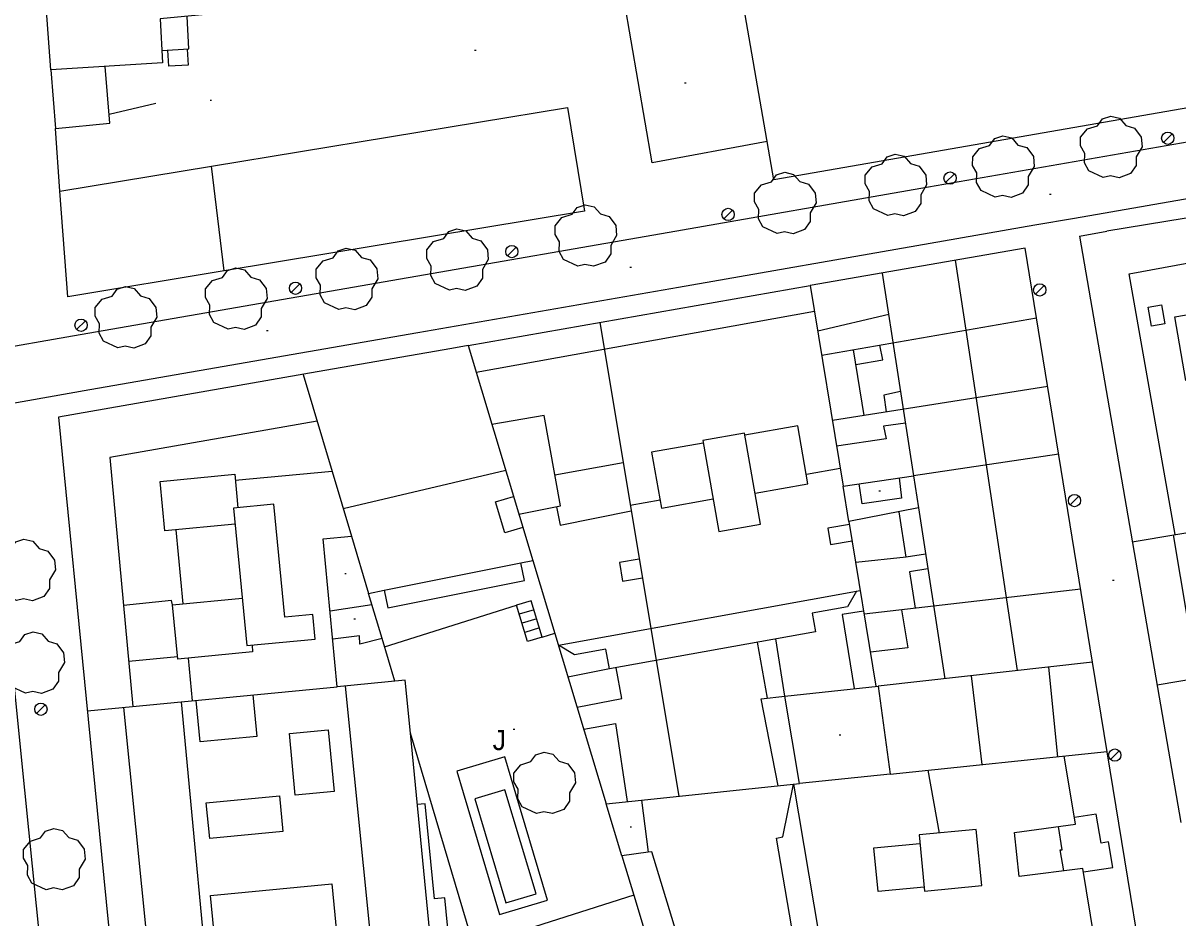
# Model space of a CAD drawing. Extents: x 431390 to 432653, y 4586754 to 4589600.
# Drawn here: x 431870.2 to 431945.3, y 4586880.3 to 4586938.4 of the extents above; entities that cross this region are included whole.
import ezdxf

# ---------------------------------------------------------------- set-up
doc = ezdxf.new("R2010")
doc.units = 0
for name, color, linetype in [('COM_17LS_LN', 7, 'Continuous'), ('CON_01_LN', 7, 'Continuous'), ('CON_01FI_LN', 7, 'Continuous'), ('CON_03_LN', 7, 'Continuous'), ('CON_04_LN', 7, 'Continuous'), ('CON_07_LN', 7, 'Continuous'), ('CON_10_LN', 7, 'Continuous'), ('CON_14LS_LN', 7, 'Continuous'), ('CON_15_LN', 7, 'Continuous'), ('CON_16_LN', 7, 'Continuous'), ('CON_17_LN', 7, 'Continuous'), ('CON_23_LN', 7, 'Continuous'), ('CON_29_LN', 7, 'Continuous'), ('ENE_06_PT', 7, 'Continuous'), ('HID_11EX_LN', 7, 'Continuous'), ('HID_11IN_LN', 7, 'Continuous'), ('ORO_03_PT', 7, 'Continuous'), ('TOP_15JA_TX', 7, 'Continuous'), ('VEG_03_PT', 7, 'Continuous'), ('VEG_06_LN', 7, 'Continuous')]:
    doc.layers.add(name, color=color, linetype=linetype)

msp = doc.modelspace()

# ---------------------------------------------------------------- linework, layer by layer
at = {"layer": 'COM_17LS_LN'}
for points in [[(431978.482, 4586940.712), (431979.21, 4586936.465), (431977.301, 4586936.133), (431968.138, 4586934.539), (431952.481, 4586931.815), (431928.554, 4586927.652), (431912.203, 4586924.807), (431895.247, 4586921.857), (431873.934, 4586918.149), (431867.46, 4586917.026), (431866.397, 4586927.581), (431865.787, 4586933.635), (431867.716, 4586933.829), (431867.112, 4586939.828), (431865.183, 4586939.634), (431863.226, 4586959.067), (431861.278, 4586978.415)], [(431938.543, 4586925.736), (431968.756, 4586930.993), (431979.572, 4586932.875)], [(431935.982, 4586925.291), (431938.543, 4586925.736)], [(431874.91, 4586845.69), (431873.853, 4586853.541), (431873.729, 4586854.767), (431875.087, 4586854.904), (431874.927, 4586856.495), (431873.569, 4586856.358), (431870.326, 4586888.559), (431867.823, 4586913.416), (431874.552, 4586914.603), (431895.864, 4586918.311), (431912.821, 4586921.261), (431929.172, 4586924.106), (431935.982, 4586925.291)]]:
    msp.add_lwpolyline(points, dxfattribs=at)
at = {"layer": 'CON_01_LN'}
for points in [[(431969.206, 4586961.566), (431973.29, 4586937.65), (431960.331, 4586935.401), (431960.23, 4586935.985), (431956.915, 4586935.41), (431957.016, 4586934.825), (431919.01, 4586928.23)], [(431872.028, 4586935.375), (431871.13, 4586947.5)], [(431906.713, 4586926.193), (431883.286, 4586922.314)], [(431948.316, 4586926.149), (431940.65, 4586924.889)], [(431938.866, 4586924.564), (431940.65, 4586924.889)], [(431938.866, 4586924.564), (431945.466, 4586886.462)], [(431935.349, 4586923.793), (431921.372, 4586921.348)], [(431939.73, 4586896.87), (431935.349, 4586923.793)], [(431899.135, 4586917.457), (431921.372, 4586921.348)], [(431899.135, 4586917.457), (431898.087, 4586917.274), (431889.328, 4586915.741), (431872.52, 4586912.8), (431874.449, 4586893.185)], [(431906.402, 4586853.218), (431945.07, 4586864.17), (431939.73, 4586896.87)], [(431874.449, 4586893.185), (431876.634, 4586870.968)]]:
    msp.add_lwpolyline(points, dxfattribs=at)
at = {"layer": 'CON_01FI_LN'}
for points in [[(431871.13, 4586947.5), (431902.33, 4586950.93), (431904.113, 4586941.087), (431879.12, 4586938.68), (431879.27, 4586935.82), (431872.028, 4586935.375)], [(431919.01, 4586928.23), (431916.429, 4586943.089)], [(431883.286, 4586922.314), (431882.464, 4586929.119), (431905.59, 4586932.93), (431906.713, 4586926.193)], [(431928.406, 4586906.9), (431923.888, 4586906.031), (431923.511, 4586908.323), (431928.084, 4586908.997), (431928.406, 4586906.9)], [(431902.571, 4586903.326), (431903.349, 4586903.481), (431908.115, 4586887.673), (431910.413, 4586887.913), (431910.843, 4586884.526), (431909.134, 4586884.293), (431909.905, 4586881.735), (431899.52, 4586878.424), (431895.383, 4586892.267), (431895.05, 4586895.7), (431890.638, 4586895.276), (431889.715, 4586904.885), (431891.559, 4586905.062), (431892.668, 4586901.35), (431893.691, 4586901.554), (431893.919, 4586900.412), (431902.799, 4586902.183), (431902.571, 4586903.326)], [(431926.567, 4586889.6), (431920.676, 4586888.985), (431919.73, 4586894.66), (431925.783, 4586895.329), (431926.567, 4586889.6)]]:
    msp.add_lwpolyline(points, dxfattribs=at)
at = {"layer": 'CON_03_LN'}
for points in [[(431921.372, 4586921.348), (431923.511, 4586908.323)], [(431936.09, 4586919.24), (431922.117, 4586916.812)], [(431899.135, 4586917.457), (431903.349, 4586903.481)], [(431888.415, 4586915.581), (431891.559, 4586905.062)], [(431936.813, 4586914.796), (431922.811, 4586912.586)], [(431937.53, 4586910.39), (431928.084, 4586908.997)], [(431942.306, 4586904.706), (431960.49, 4586907.75), (431961.044, 4586904.615)], [(431923.888, 4586906.031), (431925.648, 4586895.314)], [(431938.956, 4586901.624), (431924.877, 4586900.008)], [(431943.915, 4586895.416), (431962.128, 4586898.474)], [(431939.73, 4586896.87), (431925.783, 4586895.329)], [(431874.397, 4586893.717), (431890.638, 4586895.276)], [(431926.567, 4586889.6), (431940.676, 4586891.074)], [(431910.413, 4586887.913), (431920.676, 4586888.985)], [(431909.905, 4586881.735), (431911.79, 4586875.485)]]:
    msp.add_lwpolyline(points, dxfattribs=at)
at = {"layer": 'CON_04_LN'}
for points in [[(431945.101, 4586905.174), (431942.11, 4586922.12), (431948.803, 4586923.36)], [(431926.058, 4586922.168), (431928.084, 4586908.997)], [(431921.648, 4586919.669), (431899.666, 4586915.697)], [(431926.473, 4586919.471), (431921.858, 4586918.39)], [(431943.327, 4586919.951), (431944.195, 4586920.104), (431944.414, 4586918.862), (431943.546, 4586918.709), (431943.327, 4586919.951)], [(431948.306, 4586915.632), (431945.779, 4586915.191), (431945.06, 4586919.312), (431947.587, 4586919.753), (431948.306, 4586915.632)], [(431907.689, 4586918.954), (431912.841, 4586888.167)], [(431924.874, 4586912.912), (431924.182, 4586917.171)], [(431924.335, 4586916.232), (431926.09, 4586916.52), (431925.908, 4586917.471)], [(431927.242, 4586914.473), (431926.16, 4586914.23), (431926.309, 4586913.138)], [(431902.44, 4586906.497), (431905.14, 4586907.03), (431904.08, 4586912.91), (431900.681, 4586912.33)], [(431889.323, 4586912.543), (431875.86, 4586910.18), (431877.351, 4586894.001)], [(431917.784, 4586907.867), (431921.227, 4586908.473), (431920.567, 4586912.229), (431917.124, 4586911.623)], [(431927.558, 4586912.417), (431926.14, 4586912.21), (431926.3, 4586911.4), (431923.086, 4586910.913)], [(431914.419, 4586911.116), (431911.063, 4586910.526), (431911.701, 4586906.898), (431915.057, 4586907.488)], [(431918.14, 4586905.843), (431917.1, 4586911.759), (431914.39, 4586911.282), (431915.43, 4586905.367), (431918.14, 4586905.843)], [(431904.775, 4586909.054), (431909.212, 4586909.854)], [(431883.995, 4586905.849), (431879.43, 4586905.411), (431879.122, 4586908.622), (431883.969, 4586909.087), (431884.177, 4586906.92)], [(431884.006, 4586908.697), (431890.292, 4586909.3)], [(431901.584, 4586909.334), (431891.026, 4586906.847)], [(431923.323, 4586909.465), (431921.121, 4586909.078)], [(431902.698, 4586905.639), (431901.525, 4586905.285), (431900.919, 4586907.295), (431902.092, 4586907.649)], [(431911.612, 4586907.406), (431909.678, 4586907.066)], [(431889.205, 4586898.385), (431889.052, 4586899.978), (431887.222, 4586899.802), (431886.517, 4586907.145), (431883.895, 4586906.893), (431884.753, 4586897.958), (431889.205, 4586898.385)], [(431904.887, 4586906.98), (431905.121, 4586905.793), (431909.739, 4586906.704)], [(431928.868, 4586903.896), (431927.605, 4586903.702), (431927.15, 4586906.658)], [(431928.406, 4586906.9), (431930.112, 4586895.807)], [(431880.621, 4586900.668), (431880.159, 4586905.481)], [(431923.921, 4586905.829), (431922.521, 4586905.599), (431922.697, 4586904.528), (431924.097, 4586904.758)], [(431944.973, 4586905.152), (431948.089, 4586886.597)], [(431927.605, 4586903.702), (431924.329, 4586903.347)], [(431893.691, 4586901.554), (431902.571, 4586903.326)], [(431910.264, 4586903.566), (431908.967, 4586903.349), (431909.17, 4586902.138), (431910.467, 4586902.355)], [(431929.015, 4586902.941), (431927.824, 4586902.758), (431928.188, 4586900.388)], [(431924.378, 4586901.488), (431923.79, 4586900.48), (431921.501, 4586900.067), (431921.72, 4586898.85), (431908.327, 4586896.436), (431908.096, 4586897.719), (431906.05, 4586897.35), (431905.003, 4586897.994), (431924.627, 4586901.533)], [(431879.926, 4586900.601), (431879.86, 4586900.88), (431876.747, 4586900.552)], [(431885.092, 4586897.991), (431885.135, 4586897.544), (431880.265, 4586897.076), (431879.926, 4586900.601), (431884.457, 4586901.036)], [(431924.846, 4586900.198), (431923.447, 4586899.968), (431924.237, 4586895.158)], [(431927.307, 4586900.287), (431927.71, 4586897.81), (431925.284, 4586897.529)], [(431919.287, 4586888.84), (431918.18, 4586894.49), (431919.73, 4586894.66), (431919.145, 4586898.386)], [(431918.605, 4586894.537), (431917.953, 4586898.171)], [(431880.25, 4586897.235), (431877.082, 4586896.922)], [(431881.226, 4586894.373), (431880.96, 4586897.143)], [(431908.327, 4586896.436), (431905.63, 4586895.915)], [(431906.218, 4586893.965), (431909.12, 4586894.52), (431908.759, 4586896.514)], [(431936.857, 4586896.553), (431937.438, 4586890.736)], [(431931.836, 4586895.998), (431932.522, 4586890.222)], [(431885.156, 4586894.75), (431885.415, 4586892.056), (431881.722, 4586891.701), (431881.463, 4586894.395)], [(431893.498, 4586872.001), (431891.179, 4586895.328)], [(431876.73, 4586893.941), (431879.089, 4586870.671)], [(431880.49, 4586894.302), (431882.687, 4586871.003)], [(431887.524, 4586892.244), (431890.045, 4586892.482), (431890.422, 4586888.482), (431887.901, 4586888.244), (431887.524, 4586892.244)], [(431906.653, 4586892.521), (431908.72, 4586892.89), (431909.474, 4586887.815)], [(431897.318, 4586872.354), (431895.383, 4586892.267)], [(431939.833, 4586878.985), (431939.091, 4586883.467), (431934.96, 4586882.95), (431934.66, 4586885.82), (431938.613, 4586886.356), (431937.881, 4586890.782)], [(431922.29, 4586877.13), (431920.481, 4586879.675), (431920.177, 4586879.624), (431919.192, 4586885.45), (431919.596, 4586885.518), (431920.293, 4586888.945), (431922.29, 4586877.13)], [(431882.122, 4586887.748), (431886.883, 4586888.197), (431887.102, 4586885.874), (431882.341, 4586885.425), (431882.122, 4586887.748)], [(431896.978, 4586875.852), (431897.713, 4586875.923), (431897.579, 4586877.303), (431898.027, 4586877.347), (431897.617, 4586881.564), (431896.953, 4586881.499), (431896.352, 4586887.683), (431895.833, 4586887.633)], [(431939.125, 4586883.264), (431941.05, 4586883.54), (431940.77, 4586885.21), (431940.29, 4586885.11), (431939.96, 4586887), (431938.541, 4586886.789)], [(431932.521, 4586882.358), (431932.166, 4586886.01), (431928.446, 4586885.648), (431928.801, 4586881.996), (431932.521, 4586882.358)], [(431937.865, 4586883.314), (431937.61, 4586884.68), (431937.75, 4586884.69), (431937.5, 4586886.205)], [(431928.775, 4586882.26), (431925.787, 4586881.97), (431925.511, 4586884.813), (431928.499, 4586885.103)], [(431911.112, 4586877.732), (431912.975, 4586878.293), (431911.086, 4586884.559), (431910.843, 4586884.526)], [(431882.398, 4586881.722), (431890.283, 4586882.466), (431890.705, 4586877.993), (431882.82, 4586877.249), (431882.398, 4586881.722)]]:
    msp.add_lwpolyline(points, dxfattribs=at)
at = {"layer": 'CON_07_LN'}
for points in [[(431879.227, 4586936.639), (431880.994, 4586936.732), (431880.882, 4586938.85)], [(431872.028, 4586935.375), (431872.31, 4586931.567), (431875.86, 4586931.9), (431875.559, 4586935.592)], [(431927.158, 4586908.861), (431927.31, 4586907.53), (431924.75, 4586907.16), (431924.549, 4586908.476)], [(431894.376, 4586895.635), (431893.545, 4586898.416), (431892.11, 4586898.05), (431892.07, 4586898.59), (431890.341, 4586898.367)]]:
    msp.add_lwpolyline(points, dxfattribs=at)
at = {"layer": 'CON_10_LN'}
msp.add_lwpolyline([(431883.286, 4586922.314), (431873.12, 4586920.63), (431872.611, 4586927.496), (431882.464, 4586929.119)], dxfattribs=at)
at = {"layer": 'CON_14LS_LN'}
msp.add_lwpolyline([(431875.811, 4586932.496), (431878.85, 4586933.21)], dxfattribs=at)
at = {"layer": 'CON_15_LN'}
msp.add_lwpolyline([(431880.886, 4586936.726), (431880.941, 4586935.672), (431879.676, 4586935.606), (431879.621, 4586936.66)], dxfattribs=at)
at = {"layer": 'CON_16_LN'}
for points in [[(431872.611, 4586927.496), (431872.31, 4586931.567)], [(431892.89, 4586900.607), (431890.166, 4586900.188)], [(431893.545, 4586898.416), (431892.668, 4586901.35)], [(431909.134, 4586884.293), (431908.115, 4586887.673)]]:
    msp.add_lwpolyline(points, dxfattribs=at)
at = {"layer": 'CON_17_LN'}
msp.add_lwpolyline([(431918.578, 4586930.718), (431911.1, 4586929.32), (431909.29, 4586939.91), (431916.429, 4586943.089)], dxfattribs=at)
at = {"layer": 'CON_23_LN'}
for points in [[(431903.956, 4586898.515), (431903.245, 4586900.874), (431902.288, 4586900.585)], [(431903.956, 4586898.515), (431902.999, 4586898.226), (431902.288, 4586900.585)], [(431903.423, 4586900.284), (431902.465, 4586899.996)], [(431903.601, 4586899.694), (431902.643, 4586899.406)], [(431903.778, 4586899.105), (431902.821, 4586898.816)]]:
    msp.add_lwpolyline(points, dxfattribs=at)
at = {"layer": 'CON_29_LN'}
for points in [[(431931.514, 4586918.445), (431930.826, 4586923.002)], [(431934.847, 4586896.331), (431931.514, 4586918.445)], [(431929.016, 4586889.856), (431929.744, 4586885.774)]]:
    msp.add_lwpolyline(points, dxfattribs=at)
at = {"layer": 'ENE_06_PT'}
for p, q in [((431944.892, 4586931.212), (431944.326, 4586930.646)), ((431930.742, 4586928.622), (431930.176, 4586928.056)), ((431916.322, 4586926.262), (431915.756, 4586925.696)), ((431902.262, 4586923.842), (431901.696, 4586923.276)), ((431888.202, 4586921.462), (431887.636, 4586920.896)), ((431936.572, 4586921.352), (431936.006, 4586920.786)), ((431874.262, 4586919.062), (431873.696, 4586918.496)), ((431938.832, 4586907.662), (431938.266, 4586907.096)), ((431871.652, 4586894.102), (431871.086, 4586893.536)), ((431941.452, 4586891.122), (431940.886, 4586890.556))]:
    msp.add_line(p, q, dxfattribs=at)
for centre in [(431944.609, 4586930.929), (431930.459, 4586928.339), (431916.039, 4586925.979), (431901.979, 4586923.559), (431887.919, 4586921.179), (431936.289, 4586921.069), (431873.979, 4586918.779), (431938.549, 4586907.379), (431871.369, 4586893.819), (431941.169, 4586890.839)]:
    msp.add_circle(centre, 0.4, dxfattribs=at)
at = {"layer": 'HID_11EX_LN'}
msp.add_lwpolyline([(431901.933, 4586889.332), (431901.514, 4586890.733), (431898.401, 4586889.803), (431898.82, 4586888.401), (431901.186, 4586880.484), (431904.299, 4586881.415), (431901.933, 4586889.332)], dxfattribs=at)
at = {"layer": 'HID_11IN_LN'}
msp.add_lwpolyline([(431901.589, 4586881.231), (431903.552, 4586881.818), (431901.53, 4586888.585), (431899.567, 4586887.998), (431901.589, 4586881.231)], dxfattribs=at)
at = {"layer": 'ORO_03_PT'}
for p, q in [((431899.56, 4586936.65), (431899.66, 4586936.65)), ((431913.2, 4586934.52), (431913.3, 4586934.52)), ((431882.37, 4586933.4), (431882.47, 4586933.4)), ((431936.923, 4586927.29), (431937.023, 4586927.29)), ((431909.656, 4586922.546), (431909.756, 4586922.546)), ((431886.039, 4586918.437), (431886.139, 4586918.437)), ((431925.84, 4586908.02), (431925.94, 4586908.02)), ((431891.12, 4586902.65), (431891.22, 4586902.65)), ((431941.023, 4586902.217), (431941.123, 4586902.217)), ((431891.72, 4586899.69), (431891.82, 4586899.69)), ((431902.07, 4586892.52), (431902.17, 4586892.52)), ((431923.26, 4586892.15), (431923.36, 4586892.15)), ((431909.66, 4586886.17), (431909.76, 4586886.17))]:
    msp.add_line(p, q, dxfattribs=at)
at = {"layer": 'VEG_03_PT'}
for points in [[(431940.414, 4586928.371), (431939.487, 4586928.806), (431939.199, 4586929.327), (431939.222, 4586929.941), (431938.94, 4586930.433), (431938.948, 4586930.996), (431939.389, 4586931.531), (431940.042, 4586931.735), (431940.377, 4586932.186), (431940.903, 4586932.356), (431941.483, 4586932.223), (431941.883, 4586931.757), (431942.457, 4586931.587), (431942.891, 4586931.004), (431942.94, 4586930.362), (431942.557, 4586929.715), (431942.557, 4586929.165), (431942.185, 4586928.631), (431941.446, 4586928.356), (431940.881, 4586928.484), (431940.414, 4586928.371)], [(431933.404, 4586927.101), (431932.477, 4586927.536), (431932.189, 4586928.057), (431932.212, 4586928.671), (431931.93, 4586929.163), (431931.938, 4586929.726), (431932.379, 4586930.261), (431933.032, 4586930.465), (431933.367, 4586930.916), (431933.893, 4586931.086), (431934.473, 4586930.953), (431934.873, 4586930.487), (431935.447, 4586930.317), (431935.881, 4586929.734), (431935.93, 4586929.092), (431935.547, 4586928.445), (431935.547, 4586927.895), (431935.175, 4586927.361), (431934.436, 4586927.086), (431933.871, 4586927.214), (431933.404, 4586927.101)], [(431926.414, 4586925.901), (431925.487, 4586926.336), (431925.199, 4586926.857), (431925.222, 4586927.471), (431924.94, 4586927.963), (431924.948, 4586928.526), (431925.389, 4586929.061), (431926.042, 4586929.265), (431926.377, 4586929.716), (431926.903, 4586929.886), (431927.483, 4586929.753), (431927.883, 4586929.287), (431928.457, 4586929.117), (431928.891, 4586928.534), (431928.94, 4586927.892), (431928.557, 4586927.245), (431928.557, 4586926.695), (431928.185, 4586926.161), (431927.446, 4586925.886), (431926.881, 4586926.014), (431926.414, 4586925.901)], [(431919.224, 4586924.731), (431918.297, 4586925.166), (431918.009, 4586925.687), (431918.032, 4586926.301), (431917.75, 4586926.793), (431917.758, 4586927.356), (431918.199, 4586927.891), (431918.852, 4586928.095), (431919.187, 4586928.546), (431919.713, 4586928.716), (431920.293, 4586928.583), (431920.693, 4586928.117), (431921.267, 4586927.947), (431921.701, 4586927.364), (431921.75, 4586926.722), (431921.367, 4586926.075), (431921.367, 4586925.525), (431920.995, 4586924.991), (431920.256, 4586924.716), (431919.691, 4586924.844), (431919.224, 4586924.731)], [(431906.264, 4586922.621), (431905.337, 4586923.056), (431905.049, 4586923.577), (431905.072, 4586924.191), (431904.79, 4586924.683), (431904.798, 4586925.246), (431905.239, 4586925.781), (431905.892, 4586925.985), (431906.227, 4586926.436), (431906.753, 4586926.606), (431907.333, 4586926.473), (431907.733, 4586926.007), (431908.307, 4586925.837), (431908.741, 4586925.254), (431908.79, 4586924.612), (431908.407, 4586923.965), (431908.407, 4586923.415), (431908.035, 4586922.881), (431907.296, 4586922.606), (431906.731, 4586922.734), (431906.264, 4586922.621)], [(431897.924, 4586921.051), (431896.997, 4586921.486), (431896.709, 4586922.007), (431896.732, 4586922.621), (431896.45, 4586923.113), (431896.458, 4586923.676), (431896.899, 4586924.211), (431897.552, 4586924.415), (431897.887, 4586924.866), (431898.413, 4586925.036), (431898.993, 4586924.903), (431899.393, 4586924.437), (431899.967, 4586924.267), (431900.401, 4586923.684), (431900.45, 4586923.042), (431900.067, 4586922.395), (431900.067, 4586921.845), (431899.695, 4586921.311), (431898.956, 4586921.036), (431898.391, 4586921.164), (431897.924, 4586921.051)], [(431890.734, 4586919.801), (431889.807, 4586920.236), (431889.519, 4586920.757), (431889.542, 4586921.371), (431889.26, 4586921.863), (431889.268, 4586922.426), (431889.709, 4586922.961), (431890.362, 4586923.165), (431890.697, 4586923.616), (431891.223, 4586923.786), (431891.803, 4586923.653), (431892.203, 4586923.187), (431892.777, 4586923.017), (431893.211, 4586922.434), (431893.26, 4586921.792), (431892.877, 4586921.145), (431892.877, 4586920.595), (431892.505, 4586920.061), (431891.766, 4586919.786), (431891.201, 4586919.914), (431890.734, 4586919.801)], [(431883.544, 4586918.521), (431882.617, 4586918.956), (431882.329, 4586919.477), (431882.352, 4586920.091), (431882.07, 4586920.583), (431882.078, 4586921.146), (431882.519, 4586921.681), (431883.172, 4586921.885), (431883.507, 4586922.336), (431884.033, 4586922.506), (431884.613, 4586922.373), (431885.013, 4586921.907), (431885.587, 4586921.737), (431886.021, 4586921.154), (431886.07, 4586920.512), (431885.687, 4586919.865), (431885.687, 4586919.315), (431885.315, 4586918.781), (431884.576, 4586918.506), (431884.011, 4586918.634), (431883.544, 4586918.521)], [(431876.374, 4586917.301), (431875.447, 4586917.736), (431875.159, 4586918.257), (431875.182, 4586918.871), (431874.9, 4586919.363), (431874.908, 4586919.926), (431875.349, 4586920.461), (431876.002, 4586920.665), (431876.337, 4586921.116), (431876.863, 4586921.286), (431877.443, 4586921.153), (431877.843, 4586920.687), (431878.417, 4586920.517), (431878.851, 4586919.934), (431878.9, 4586919.292), (431878.517, 4586918.645), (431878.517, 4586918.095), (431878.145, 4586917.561), (431877.406, 4586917.286), (431876.841, 4586917.414), (431876.374, 4586917.301)], [(431869.784, 4586900.881), (431868.857, 4586901.316), (431868.569, 4586901.837), (431868.592, 4586902.451), (431868.31, 4586902.943), (431868.318, 4586903.506), (431868.759, 4586904.041), (431869.412, 4586904.245), (431869.747, 4586904.696), (431870.273, 4586904.866), (431870.853, 4586904.733), (431871.253, 4586904.267), (431871.827, 4586904.097), (431872.261, 4586903.514), (431872.31, 4586902.872), (431871.927, 4586902.225), (431871.927, 4586901.675), (431871.555, 4586901.141), (431870.816, 4586900.866), (431870.251, 4586900.994), (431869.784, 4586900.881)], [(431870.374, 4586894.861), (431869.447, 4586895.296), (431869.159, 4586895.817), (431869.182, 4586896.431), (431868.9, 4586896.923), (431868.908, 4586897.486), (431869.349, 4586898.021), (431870.002, 4586898.225), (431870.337, 4586898.676), (431870.863, 4586898.846), (431871.443, 4586898.713), (431871.843, 4586898.247), (431872.417, 4586898.077), (431872.851, 4586897.494), (431872.9, 4586896.852), (431872.517, 4586896.205), (431872.517, 4586895.655), (431872.145, 4586895.121), (431871.406, 4586894.846), (431870.841, 4586894.974), (431870.374, 4586894.861)], [(431903.584, 4586887.051), (431902.657, 4586887.486), (431902.369, 4586888.007), (431902.392, 4586888.621), (431902.11, 4586889.113), (431902.118, 4586889.676), (431902.559, 4586890.211), (431903.212, 4586890.415), (431903.547, 4586890.866), (431904.073, 4586891.036), (431904.653, 4586890.903), (431905.053, 4586890.437), (431905.627, 4586890.267), (431906.061, 4586889.684), (431906.11, 4586889.042), (431905.727, 4586888.395), (431905.727, 4586887.845), (431905.355, 4586887.311), (431904.616, 4586887.036), (431904.051, 4586887.164), (431903.584, 4586887.051)], [(431871.714, 4586882.091), (431870.787, 4586882.526), (431870.499, 4586883.047), (431870.522, 4586883.661), (431870.24, 4586884.153), (431870.248, 4586884.716), (431870.689, 4586885.251), (431871.342, 4586885.455), (431871.677, 4586885.906), (431872.203, 4586886.076), (431872.783, 4586885.943), (431873.183, 4586885.477), (431873.757, 4586885.307), (431874.191, 4586884.724), (431874.24, 4586884.082), (431873.857, 4586883.435), (431873.857, 4586882.885), (431873.485, 4586882.351), (431872.746, 4586882.076), (431872.181, 4586882.204), (431871.714, 4586882.091)]]:
    msp.add_lwpolyline(points, dxfattribs=at)
at = {"layer": 'VEG_06_LN'}
for points in [[(431893.703, 4586897.887), (431902.288, 4586900.585)], [(431903.956, 4586898.515), (431904.772, 4586898.761)]]:
    msp.add_lwpolyline(points, dxfattribs=at)

# ---------------------------------------------------------------- texts
at = {"layer": 'TOP_15JA_TX'}
msp.add_text('J', height=1.3, dxfattribs=at).set_placement((431900.73, 4586891.165))

doc.saveas('drawing.dxf')
